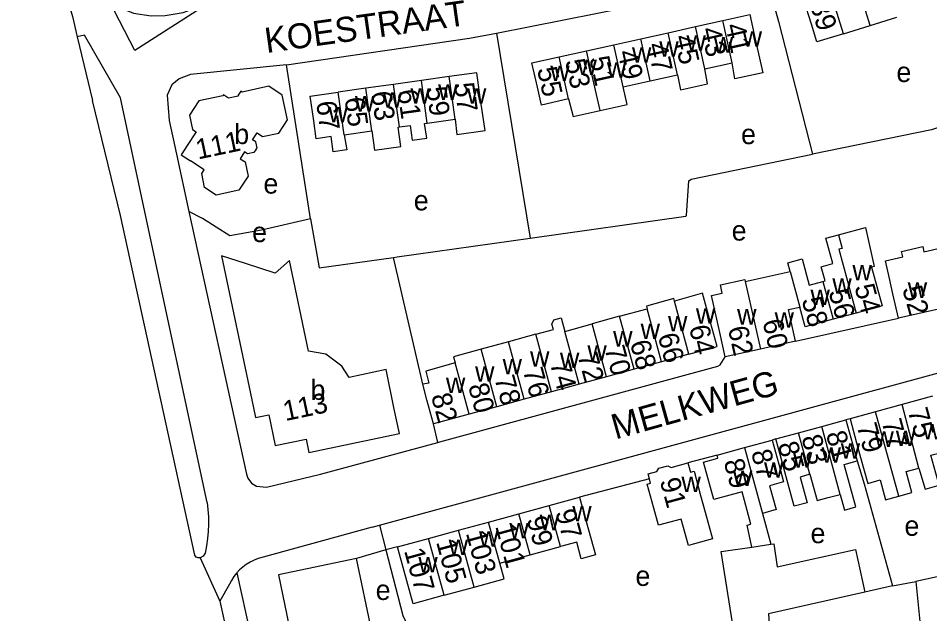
# Model space of a CAD drawing. Extents: x 163012 to 165277, y 382513 to 383987.
# Drawn here: x 163085.6 to 163267.3, y 383657.3 to 383776.1 of the extents above; entities that cross this region are included whole.
import ezdxf

# ---------------------------------------------------------------- set-up
doc = ezdxf.new("R2010")
doc.units = 0
for name, color, linetype in [('BLT_Basislijn', 7, 'Continuous'), ('BLT_Bebouwing', 7, 'Continuous'), ('BLT_Centroide', 7, 'Continuous'), ('BLT_Huisnummer', 7, 'Continuous'), ('BLT_Huisnummer_ tussenligend', 7, 'Continuous'), ('BLT_Onderverdeling_panden', 7, 'Continuous'), ('BLT_Straatnaam', 7, 'Continuous'), ('BLT_Vlakafsluiter', 7, 'Continuous')]:
    doc.layers.add(name, color=color, linetype=linetype)

msp = doc.modelspace()

# ---------------------------------------------------------------- linework, layer by layer
at = {"layer": 'BLT_Basislijn'}
for p, q in [((163097.41, 383772.45), (163100.45, 383759.73)), ((163180.96, 383773.16), (163187.68, 383732.24)), ((163143.9, 383736.14), (163139.12, 383766.82)), ((163166.26, 383703.13), (163160.42, 383728.41)), ((163240.57, 383711.71), (163261.12, 383716.28)), ((163169.25, 383691.5), (163168.42, 383695.19)), ((163251.44, 383696.23), (163250.63, 383696.03)), ((163236.67, 383692.22), (163235.9, 383691.98)), ((163224.93, 383688.99), (163219.13, 383687.42)), ((163211.47, 383684.26), (163197.53, 383680.58)), ((163156.16, 383674.58), (163133.74, 383668.41)), ((163156.16, 383674.58), (163157.64, 383674.98)), ((163157.64, 383674.98), (163158.9, 383670.1)), ((163158.9, 383670.1), (163153.08, 383668.35)), ((163161.26, 383670.65), (163158.9, 383670.1)), ((163133.74, 383668.41), (163133.45, 383668.33)), ((163129.23, 383665.51), (163129.14, 383665.42)), ((163129.23, 383665.51), (163137.03, 383629.85)), ((163273.85, 383665.79), (163264.55, 383663.73)), ((163259.89, 383662.87), (163264.55, 383663.73)), ((163264.55, 383663.73), (163266.82, 383640.7))]:
    msp.add_line(p, q, dxfattribs=at)
for points in [[(163085.63, 383812.71), (163096.44, 383776.52), (163097.41, 383772.45)], [(163180.96, 383773.16), (163214.54, 383779.85), (163234.56, 383784.91)], [(163234.56, 383784.91), (163237.2, 383775.49), (163243.93, 383749)], [(163106.04, 383760.29), (163098.87, 383772.79), (163097.41, 383772.45)], [(163139.12, 383766.82), (163175.59, 383772.14), (163180.96, 383773.16)], [(163139.12, 383766.82), (163119.94, 383764.89), (163117.71, 383764.07), (163116.28, 383762.83), (163115.29, 383760.78), (163115.71, 383755.71), (163117.18, 383749.05), (163119.65, 383737.55)], [(163298.98, 383764.61), (163267.7, 383753.9), (163243.93, 383749)], [(163120.81, 383669.01), (163106.04, 383736.79), (163100.45, 383759.73)], [(163123.26, 383679.53), (163110.89, 383737.54), (163106.04, 383760.29)], [(163187.68, 383732.24), (163218.71, 383736.63), (163218.87, 383736.79), (163219.32, 383743.73), (163219.79, 383744.01), (163243.93, 383749)], [(163143.9, 383736.14), (163134.13, 383733.85), (163127.84, 383732.74), (163122.35, 383736.16), (163119.65, 383737.55)], [(163119.65, 383737.55), (163131.12, 383685.18), (163131.39, 383684.36), (163132.1, 383683.38), (163133.15, 383682.8), (163135.12, 383682.6), (163145.88, 383685.15), (163169.25, 383691.5)], [(163143.9, 383736.14), (163145.61, 383726.37), (163160.42, 383728.41)], [(163160.42, 383728.41), (163161.2, 383728.52), (163187.68, 383732.24)], [(163157.64, 383674.98), (163300.05, 383713.83), (163312.91, 383717.09)], [(163169.25, 383691.5), (163169.69, 383691.62), (163225.08, 383706.71), (163225.55, 383706.97), (163226.58, 383708.58)], [(163252.87, 383687.83), (163254.25, 383683.27), (163259.89, 383662.87)], [(163123.26, 383679.53), (163123.45, 383678.1), (163123.55, 383676.66), (163123.57, 383675.21), (163123.51, 383673.77), (163123.37, 383672.33), (163123.15, 383670.9), (163122.88, 383669.41), (163122.52, 383668.83), (163121.93, 383668.48)], [(163158.9, 383670.1), (163162.32, 383656.97), (163167.56, 383645.78)], [(163121.93, 383668.48), (163121.49, 383668.49), (163121.11, 383668.65), (163120.81, 383669.01)], [(163133.45, 383668.33), (163132.63, 383668.02), (163131.84, 383667.63), (163131.09, 383667.17), (163130.39, 383666.65), (163129.74, 383666.06), (163129.23, 383665.51)], [(163129.14, 383665.42), (163128.61, 383664.73), (163128.14, 383663.99), (163127.74, 383663.21), (163125.83, 383659.87)], [(163259.89, 383662.87), (163254.39, 383661.65)], [(163125.83, 383659.87), (163128.9, 383646.02), (163127.35, 383638.96), (163128.13, 383635.56)]]:
    msp.add_lwpolyline(points, dxfattribs=at)
msp.add_lwpolyline([(163103.74, 383779.61), (163105.37, 383778.45), (163108.62, 383777.17), (163112.11, 383776.59), (163114.9, 383776.71), (163118.5, 383777.29), (163123.61, 383779.15), (163108.85, 383769.73)], close=True, dxfattribs=at)
at = {"layer": 'BLT_Bebouwing'}
for p, q in [((163220.63, 383774.47), (163226.06, 383775.67)), ((163255.46, 383774.69), (163260.78, 383776.33)), ((163209.77, 383772.06), (163215.2, 383773.26)), ((163215.2, 383773.26), (163220.63, 383774.47)), ((163250.15, 383773.05), (163255.46, 383774.69)), ((163204.34, 383770.85), (163209.77, 383772.06)), ((163193.48, 383768.44), (163198.91, 383769.65)), ((163198.91, 383769.65), (163204.34, 383770.85)), ((163222.49, 383766.05), (163227.93, 383767.22)), ((163171.52, 383764.51), (163165.99, 383763.73)), ((163211.63, 383763.64), (163217.06, 383764.84)), ((163160.45, 383762.95), (163154.92, 383762.17)), ((163165.99, 383763.73), (163160.45, 383762.95)), ((163206.2, 383762.43), (163211.63, 383763.64)), ((163154.92, 383762.17), (163149.38, 383761.39)), ((163167.18, 383755.23), (163172.71, 383756)), ((163150.58, 383752.89), (163156.11, 383753.67)), ((163119.32, 383750.72), (163118.84, 383750)), ((163230.55, 383723.62), (163239.5, 383725.62)), ((163239.16, 383718.01), (163241.42, 383718.51)), ((163240.57, 383711.71), (163239.16, 383718.01)), ((163252.67, 383717.33), (163248.07, 383716.09)), ((163269.05, 383718.07), (163261.12, 383716.28)), ((163194.58, 383713.62), (163200.05, 383715.15)), ((163205.52, 383716.68), (163200.05, 383715.15)), ((163183.36, 383711.59), (163177.88, 383710.1)), ((163188.83, 383713.09), (163183.36, 383711.59)), ((163240.57, 383711.71), (163233.58, 383710.14)), ((163233.58, 383710.14), (163226.58, 383708.58)), ((163219.32, 383709.09), (163213.88, 383707.61)), ((163208.4, 383706.11), (163202.92, 383704.62)), ((163213.88, 383707.61), (163208.4, 383706.11)), ((163202.92, 383704.62), (163197.45, 383703.12)), ((163197.45, 383703.12), (163191.96, 383701.62)), ((163191.96, 383701.62), (163186.49, 383700.13)), ((163267.9, 383700.72), (163261.81, 383699.06)), ((163186.49, 383700.13), (163181.01, 383698.63)), ((163261.81, 383699.06), (163256.55, 383697.62)), ((163175.53, 383697.13), (163168.42, 383695.19)), ((163181.01, 383698.63), (163175.53, 383697.13)), ((163256.55, 383697.62), (163251.44, 383696.23)), ((163245.8, 383694.71), (163250.63, 383696.03)), ((163236.67, 383692.22), (163241.19, 383693.45)), ((163241.19, 383693.45), (163245.8, 383694.71)), ((163230.42, 383690.48), (163235.9, 383691.98)), ((163224.93, 383688.99), (163230.42, 383690.48)), ((163191.49, 383678.92), (163197.53, 383680.58)), ((163185.44, 383677.27), (163191.49, 383678.92)), ((163179.39, 383675.61), (163185.44, 383677.27)), ((163234, 383677.36), (163235.68, 383671.2)), ((163173.41, 383673.98), (163179.39, 383675.61)), ((163167.43, 383672.34), (163173.41, 383673.98)), ((163161.26, 383670.65), (163167.43, 383672.34)), ((163187.68, 383669.09), (163193.72, 383670.74)), ((163156.02, 383654.11), (163153.08, 383668.35)), ((163181.63, 383667.43), (163187.68, 383669.09)), ((163170.53, 383661.02), (163176.51, 383662.65))]:
    msp.add_line(p, q, dxfattribs=at)
for points in [[(163250.15, 383773.05), (163244.83, 383771.41), (163243.74, 383774.96), (163242.26, 383779.74), (163247.58, 383781.38)], [(163226.06, 383775.67), (163231.48, 383776.87), (163232.56, 383771.99), (163234.05, 383765.27), (163228.49, 383764.04), (163227.93, 383767.22)], [(163195.34, 383760.03), (163189.91, 383758.82), (163189.12, 383762.36), (163188.04, 383767.24), (163193.48, 383768.44)], [(163217.06, 383764.84), (163217.68, 383761.84), (163223.06, 383763.04), (163222.49, 383766.05)], [(163172.71, 383756), (163173.03, 383752.92), (163178.68, 383753.71), (163177.74, 383760.33), (163177.05, 383765.28), (163171.52, 383764.51)], [(163133.04, 383749.99), (163133.24, 383750.3), (163133, 383751.48), (163132.36, 383751.89), (163133.25, 383753.25), (163134.34, 383752.54), (163137.56, 383753.22), (163139.28, 383755.9), (163138.26, 383760.8), (163135.56, 383762.56), (163130.3, 383761.39), (163129.98, 383761.59), (163129.46, 383760.79), (163129.5, 383760.6), (163127.57, 383760.2), (163126.57, 383760.85), (163126.44, 383760.64), (163121.65, 383759.64), (163119.77, 383756.77), (163120.36, 383753.96), (163121.12, 383753.47), (163119.32, 383750.72)], [(163201.63, 383757.75), (163207.01, 383758.94), (163206.2, 383762.43)], [(163150.58, 383752.89), (163151.12, 383749.89), (163148.4, 383749.51), (163147.98, 383752.53), (163145.05, 383752.11), (163144.55, 383755.66), (163143.85, 383760.61), (163149.38, 383761.39)], [(163195.34, 383760.03), (163196.24, 383756.55), (163201.63, 383757.75)], [(163161.65, 383754.45), (163163.76, 383754.74), (163164.16, 383751.84), (163167.05, 383752.24), (163166.64, 383755.15), (163167.18, 383755.23)], [(163156.11, 383753.67), (163156.63, 383749.79), (163161.89, 383750.53), (163161.34, 383754.41), (163161.65, 383754.45)], [(163118.84, 383750), (163118.1, 383748.88), (163119.97, 383747.66)], [(163133.04, 383749.99), (163132.6, 383749.33), (163131.35, 383749.08), (163130.76, 383749.47), (163129.88, 383748.12), (163130.86, 383747.48), (163131.45, 383744.65), (163129.62, 383741.83), (163125.06, 383740.87), (163122.79, 383742.35), (163122.21, 383745.14), (163122.69, 383745.88), (163119.97, 383747.66)], [(163249.14, 383732.92), (163254.53, 383734.38), (163256.28, 383726.64), (163255.74, 383726.5), (163257.84, 383718.73), (163252.67, 383717.33)], [(163246.04, 383723.62), (163246.48, 383723.74), (163245.71, 383726.57), (163248.01, 383727.19), (163246.65, 383732.24), (163249.14, 383732.92)], [(163261.94, 383728.55), (163261.7, 383729.62), (163265.94, 383730.58), (163266.18, 383729.54), (163269.86, 383730.38)], [(163136.88, 383690.89), (163143.04, 383692.15), (163143.57, 383689.5), (163161.62, 383693.27), (163160.6, 383698.17), (163158.96, 383706.03), (163151.57, 383704.49), (163150.11, 383706.74), (163146.95, 383709.09), (163143.46, 383709.74), (163139.7, 383727.82), (163136.84, 383725.29), (163130.95, 383727.22), (163126.16, 383728.75), (163132.18, 383700)], [(163239.5, 383725.62), (163239.04, 383727.33), (163241.88, 383728.11), (163243.3, 383722.88), (163246.04, 383723.62)], [(163261.12, 383716.28), (163260, 383721.16), (163259.31, 383724.22), (163258.51, 383727.77), (163261.94, 383728.55)], [(163226.58, 383708.58), (163225.49, 383713.46), (163223.83, 383720.84), (163225.94, 383721.32), (163225.59, 383722.92), (163230.45, 383724.01), (163230.55, 383723.62)], [(163219.32, 383709.09), (163224.97, 383710.64), (163223.65, 383715.46), (163222.05, 383721.27), (163216.48, 383719.71)], [(163216.48, 383719.71), (163216.34, 383720.2), (163210.86, 383718.67), (163211, 383718.18)], [(163205.52, 383716.68), (163211, 383718.18)], [(163248.07, 383716.09), (163242.49, 383714.58), (163241.42, 383718.51)], [(163188.83, 383713.09), (163192.31, 383714.04), (163192.01, 383715.12), (163192.42, 383715.96), (163193.84, 383716.35), (163194.58, 383713.62)], [(163177.88, 383710.1), (163172.4, 383708.6), (163172.74, 383707.36)], [(163172.74, 383707.36), (163166.86, 383705.75), (163167.51, 383703.34), (163166.26, 383703.13)], [(163168.42, 383695.19), (163167.11, 383700.02), (163166.26, 383703.13)], [(163132.18, 383700), (163132.92, 383696.46), (163135.57, 383697.02)], [(163135.57, 383697.02), (163136.88, 383690.89)], [(163250.63, 383696.03), (163251.95, 383691.21), (163252.87, 383687.83)], [(163251.44, 383696.23), (163252.75, 383691.4), (163253.56, 383688.5), (163254.97, 383683.34), (163257.46, 383684.02), (163258.53, 383680.07), (163261.15, 383680.79)], [(163235.9, 383691.98), (163237.22, 383687.16), (163238.18, 383683.63), (163235.42, 383682.88), (163236.72, 383678.1), (163234, 383677.36)], [(163243.45, 383685.15), (163241.48, 383684.61), (163242.88, 383679.49), (163240.33, 383678.79), (163238.94, 383683.89), (163237.99, 383687.4), (163236.67, 383692.22)], [(163231.9, 383670.64), (163230.95, 383675.03), (163231.7, 383675.23), (163229.95, 383681.66), (163224.26, 383680.11), (163222.23, 383687.55), (163225.07, 383688.37), (163224.93, 383688.99)], [(163265.14, 383686.4), (163266.4, 383682.19), (163269.21, 383682.96), (163267.57, 383688.94), (163269.87, 383689.57)], [(163211.47, 383684.26), (163211.2, 383685.24), (163212.96, 383685.71), (163213.34, 383686.38), (163215.13, 383686.87), (163215.77, 383686.5), (163219.13, 383687.42)], [(163219.13, 383687.42), (163219.64, 383685.56), (163220.35, 383685.76), (163221.66, 383680.93), (163222.58, 383677.58), (163224.04, 383672.25)], [(163249.48, 383681.15), (163250.35, 383678.02), (163252.59, 383678.63), (163250.27, 383687.12), (163252.87, 383687.83)], [(163261.15, 383680.79), (163263.77, 383681.5), (163262.62, 383685.71), (163265.14, 383686.4)], [(163224.04, 383672.25), (163219.25, 383670.94), (163217.81, 383676.23), (163213.23, 383674.98), (163212.3, 383678.38), (163210.99, 383683.2), (163211.7, 383683.4), (163211.47, 383684.26)], [(163243.45, 383685.15), (163244.88, 383679.93), (163247.07, 383680.53), (163249.48, 383681.15)], [(163197.53, 383680.58), (163198.85, 383675.75), (163200.68, 383669.08), (163197.86, 383668.31), (163196.96, 383671.63), (163193.72, 383670.74)], [(163170.53, 383661.02), (163164.36, 383659.33), (163162.58, 383665.83), (163161.26, 383670.65)], [(163226.06, 383639.36), (163223.77, 383654.9), (163227.99, 383655.52), (163225.77, 383669.73), (163231.9, 383670.64)], [(163235.68, 383671.2), (163236.23, 383671.28), (163236.91, 383666.67), (163252.5, 383670.14), (163254.39, 383661.65)], [(163153.08, 383668.35), (163137.52, 383665.12), (163143.42, 383636.43)], [(163176.51, 383662.65), (163182.49, 383664.29), (163181.63, 383667.43)], [(163254.39, 383661.65), (163235.18, 383657.29), (163236.21, 383642.55)]]:
    msp.add_lwpolyline(points, dxfattribs=at)
at = {"layer": 'BLT_Onderverdeling_panden'}
for p, q in [((163255.46, 383774.69), (163252.9, 383783.02)), ((163250.15, 383773.05), (163247.58, 383781.38)), ((163227.93, 383767.22), (163226.06, 383775.67)), ((163217.06, 383764.84), (163215.2, 383773.26)), ((163222.49, 383766.05), (163220.63, 383774.47)), ((163211.63, 383763.64), (163209.77, 383772.06)), ((163201.63, 383757.75), (163198.91, 383769.65)), ((163206.2, 383762.43), (163204.34, 383770.85)), ((163195.34, 383760.03), (163193.48, 383768.44)), ((163172.71, 383756), (163171.52, 383764.51)), ((163161.65, 383754.45), (163160.45, 383762.95)), ((163167.18, 383755.23), (163165.99, 383763.73)), ((163150.58, 383752.89), (163149.38, 383761.39)), ((163156.11, 383753.67), (163154.92, 383762.17)), ((163239.5, 383725.62), (163241.42, 383718.51)), ((163230.55, 383723.62), (163233.58, 383710.14)), ((163246.04, 383723.62), (163248.07, 383716.09)), ((163219.32, 383709.09), (163216.48, 383719.71)), ((163202.92, 383704.62), (163200.05, 383715.15)), ((163208.4, 383706.11), (163205.52, 383716.68)), ((163197.45, 383703.12), (163194.58, 383713.62)), ((163186.49, 383700.13), (163183.36, 383711.59)), ((163191.96, 383701.62), (163188.83, 383713.09)), ((163181.01, 383698.63), (163177.88, 383710.1)), ((163175.53, 383697.13), (163172.74, 383707.36)), ((163265.14, 383686.4), (163261.81, 383699.06)), ((163261.15, 383680.79), (163256.55, 383697.62)), ((163243.45, 383685.15), (163241.19, 383693.45)), ((163249.48, 383681.15), (163245.8, 383694.71)), ((163230.42, 383690.48), (163234, 383677.36)), ((163193.72, 383670.74), (163191.49, 383678.92)), ((163187.68, 383669.09), (163185.44, 383677.27)), ((163181.63, 383667.43), (163179.39, 383675.61)), ((163176.51, 383662.65), (163173.41, 383673.98)), ((163170.53, 383661.02), (163167.43, 383672.34)), ((163231.9, 383670.64), (163235.68, 383671.2))]:
    msp.add_line(p, q, dxfattribs=at)
for points in [[(163249.14, 383732.92), (163249.89, 383730.21), (163249.24, 383730.04), (163252.67, 383717.33)], [(163213.88, 383707.61), (163211, 383718.18)]]:
    msp.add_lwpolyline(points, dxfattribs=at)
at = {"layer": 'BLT_Vlakafsluiter'}
msp.add_line((163121.93, 383668.48), (163125.83, 383659.87), dxfattribs=at)

# ---------------------------------------------------------------- texts
at = {"layer": 'BLT_Centroide'}
for s, p in [('w', (163230.05, 383770.47)), ('w', (163213.42, 383768.45)), ('w', (163218.84, 383769.66)), ('w', (163224.28, 383769.3)), ('w', (163207.98, 383767.25)), ('w', (163197.12, 383764.83)), ('w', (163191.69, 383763.62)), ('w', (163202.97, 383764.28)), ('e', (163260.69, 383763.41)), ('w', (163169.34, 383759.86)), ('w', (163152.75, 383757.53)), ('w', (163158.28, 383758.31)), ('w', (163163.81, 383759.09)), ('w', (163175.09, 383759.11)), ('w', (163147.47, 383755.39)), ('b', (163128.69, 383751.03)), ('e', (163229.72, 383751.02)), ('e', (163134.51, 383741.15)), ('e', (163164.48, 383737.8)), ('e', (163132.26, 383731.48)), ('e', (163227.85, 383731.78)), ('w', (163251.92, 383723.83)), ('w', (163247.92, 383721.17)), ('w', (163262.95, 383720.35)), ('w', (163243.56, 383718.91)), ('w', (163220.72, 383715.19)), ('w', (163228.93, 383715.03)), ('w', (163236.41, 383714.42)), ('w', (163209.7, 383712.14)), ('w', (163215.16, 383713.66)), ('w', (163204.22, 383710.64)), ('w', (163187.66, 383706.61)), ('w', (163199.09, 383707.83)), ('w', (163182.19, 383705.11)), ('w', (163193.62, 383706.33)), ('w', (163176.7, 383703.62)), ('b', (163143.89, 383700)), ('w', (163170.89, 383701.36)), ('w', (163265.89, 383692.12)), ('w', (163256.3, 383690.62)), ('w', (163260.58, 383690.8)), ('w', (163245.77, 383687.44)), ('w', (163249.59, 383688.28)), ('w', (163240.06, 383686.47)), ('w', (163234.3, 383684.48)), ('w', (163217.84, 383681.59)), ('w', (163228.11, 383682.8)), ('w', (163196.08, 383675.78)), ('w', (163189.58, 383674)), ('w', (163183.53, 383672.36)), ('e', (163262.29, 383672.88)), ('w', (163177.48, 383670.7)), ('e', (163243.57, 383671.4)), ('w', (163171.44, 383669.05)), ('w', (163165.39, 383665.58)), ('e', (163208.67, 383662.88)), ('e', (163156.88, 383660.08))]:
    msp.add_text(s, height=4, dxfattribs=at).set_placement(p)
at = {"layer": 'BLT_Huisnummer'}
for s, rotation, p in [('39', 287.1593, (163243.38, 383778.98)), ('41', 282.4627, (163226.53, 383774.71)), ('45', 282.4655, (163216.32, 383772.44)), ('49', 282.4625, (163205.09, 383769.4)), ('55', 282.5014, (163189.03, 383766.01)), ('57', 278.0045, (163172.49, 383763.08)), ('61', 278.0093, (163161.21, 383761.71)), ('67', 278.0021, (163145, 383759.41)), ('111', 11.8621, (163121.47, 383747.95)), ('54', 285.112, (163252.29, 383722.58)), ('52', 285.6983, (163261.82, 383722.18)), ('58', 285.1198, (163241.77, 383719.97)), ('60', 282.6389, (163233.98, 383715.68)), ('66', 285.2749, (163213.08, 383712.78)), ('64', 282.627, (163219.35, 383714.52)), ('62', 282.627, (163227.07, 383714.31)), ('70', 285.2721, (163202.48, 383710.26)), ('74', 285.2783, (163191.59, 383707.3)), ('78', 285.2765, (163180.53, 383704.31)), ('113', 11.9277, (163138.87, 383695.75)), ('82', 285.2769, (163167.89, 383700.79)), ('79', 285.2609, (163252.74, 383694.83)), ('77', 285.2609, (163257.69, 383695.63)), ('81', 285.2557, (163246.6, 383693.25)), ('85', 285.2499, (163237.02, 383691.13)), ('87', 285.2499, (163231.68, 383689.56)), ('89', 285.2557, (163226.22, 383687.69)), ('91', 285.2494, (163213.48, 383683.89)), ('97', 285.3049, (163192.68, 383677.63)), ('101', 285.3031, (163180.69, 383674.78)), ('107', 285.3094, (163162.52, 383669.91))]:
    msp.add_text(s, height=4, rotation=rotation, dxfattribs=at).set_placement(p)
at = {"layer": 'BLT_Huisnummer_ tussenligend'}
for s, rotation, p in [('43', 282.4627, (163221.68, 383773.96)), ('47', 282.4655, (163210.97, 383770.87)), ('53', 282.4625, (163194.61, 383767.61)), ('51', 282.4625, (163199.45, 383768.17)), ('59', 278.0045, (163166.95, 383762.28)), ('63', 278.0093, (163156, 383761.36)), ('65', 278.0093, (163150.66, 383760.17)), ('56', 285.112, (163247.14, 383721.59)), ('68', 285.2749, (163207.54, 383711.38)), ('72', 285.2721, (163197.1, 383708.86)), ('76', 285.2783, (163186.2, 383705.87)), ('80', 285.2765, (163175.28, 383702.77)), ('75', 285.2412, (163262.92, 383697.84)), ('83', 285.2557, (163241.73, 383692.5)), ('99', 285.3049, (163186.94, 383676.23)), ('103', 285.3031, (163174.83, 383673.43)), ('105', 285.3031, (163168.9, 383671.65))]:
    msp.add_text(s, height=4, rotation=rotation, dxfattribs=at).set_placement(p)
at = {"layer": 'BLT_Straatnaam'}
for s, rotation, p in [('KOESTRAAT', 7.9682, (163135.12, 383769.19)), ('MELKWEG', 15.5857, (163204.68, 383692.08))]:
    msp.add_text(s, height=5, rotation=rotation, dxfattribs=at).set_placement(p)

doc.saveas('drawing.dxf')
